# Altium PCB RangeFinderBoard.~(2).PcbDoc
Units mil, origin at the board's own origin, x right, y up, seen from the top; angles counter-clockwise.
Board outline 6000 x 4000 mil, 2 copper layers (Top Layer, Bottom Layer); 90 components, 55 nets, 346 pads, 0 vias.
Unrouted connection lines stored in the file: 222.
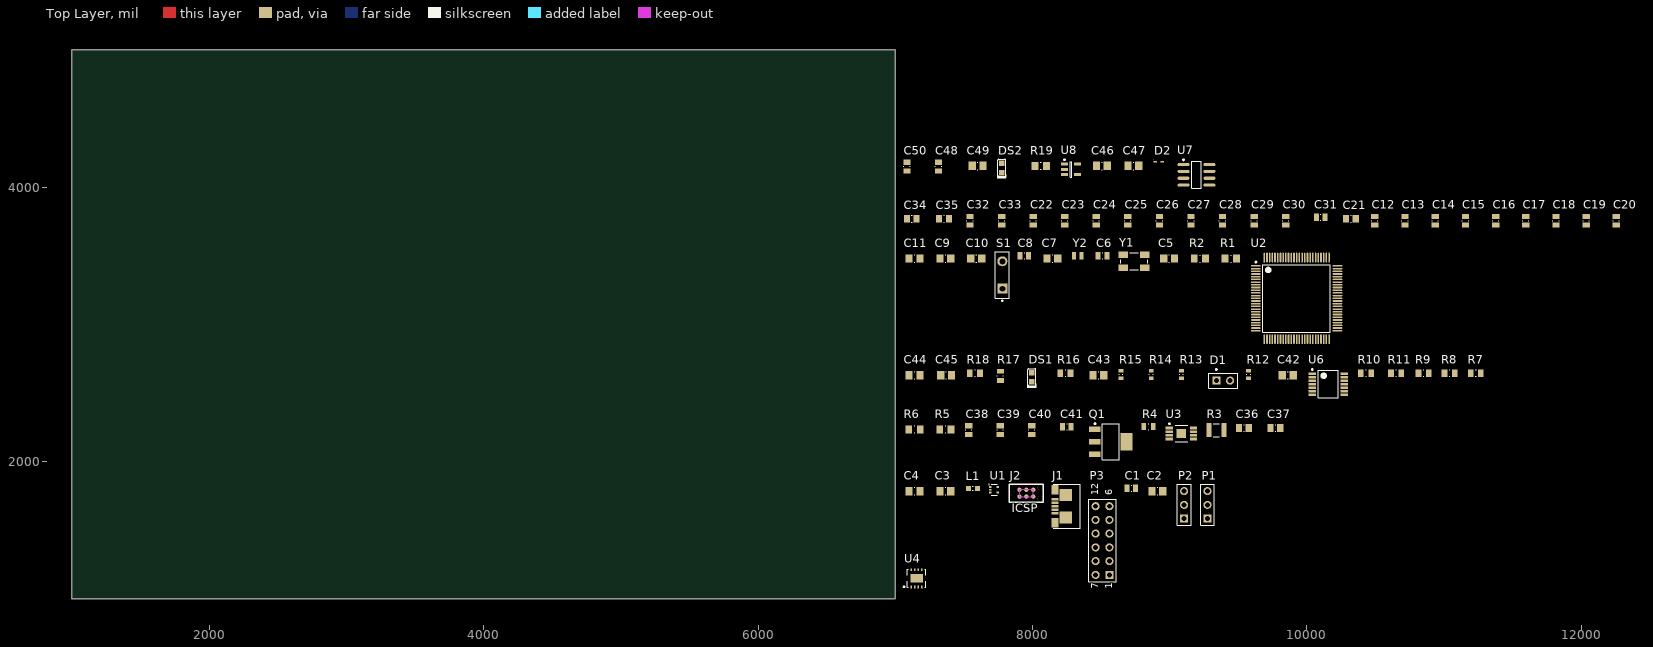
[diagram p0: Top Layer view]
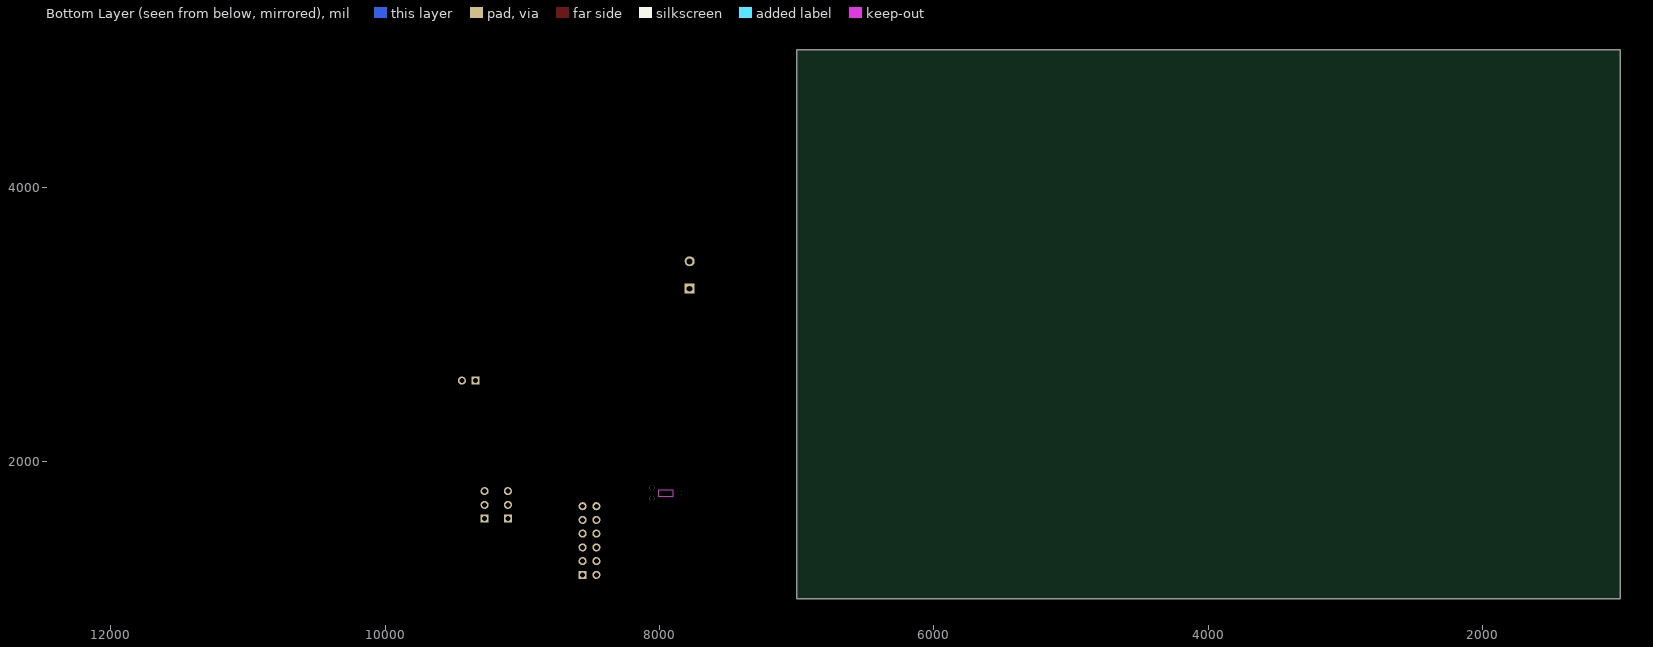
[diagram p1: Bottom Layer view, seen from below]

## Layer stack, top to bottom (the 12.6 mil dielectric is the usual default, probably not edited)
Top Solder: solder mask 0.4, Solder Resist, Dk 3.5
Top Layer: signal copper 1.4
Dielectric 1: dielectric 12.6, FR-4, Dk 4.8
Bottom Layer: signal copper 1.4
Bottom Solder: solder mask 0.4, Solder Resist, Dk 3.5

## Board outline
1000,1000 7000,1000 7000,5000 1000,5000

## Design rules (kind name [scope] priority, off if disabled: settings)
Clearance [All] p1: gap=10
PolygonConnect [All] p1: connectstyle=Relief reliefconductorwidth=10 reliefentries=4 polygonreliefangle="90 Angle" airgapwidth=10
RoomDefinition U_RangeFinderSystemPower [InComponentClass('U_RangeFinderSystemPower')] p1: confinementstyle=ConfineIn formatcopy=TRUE lockcomponents=FALSE outline 7045,3970 9350,3970 9350,4315 7045,4315
RoomDefinition U_RangeFinderMicroPower [InComponentClass('U_RangeFinderMicroPower')] p2: confinementstyle=ConfineIn formatcopy=TRUE lockcomponents=FALSE outline 7045,3690 12410,3690 12410,3920 7045,3920
RoomDefinition U_RangeFinderMicro [InComponentClass('U_RangeFinderMicro')] p3: confinementstyle=ConfineIn formatcopy=TRUE lockcomponents=FALSE outline 7045,2840 10275,2840 10275,3640 7045,3640
RoomDefinition U_LaserReceiver [InComponentClass('U_LaserReceiver')] p4: confinementstyle=ConfineIn formatcopy=TRUE lockcomponents=FALSE outline 7045,2445 11305,2445 11305,2790 7045,2790
RoomDefinition U_LaserOut [InComponentClass('U_LaserOut')] p5: confinementstyle=ConfineIn formatcopy=TRUE lockcomponents=FALSE outline 7045,1995 9890,1995 9890,2395 7045,2395
RoomDefinition RangeFinderTop [InComponentClass('RangeFinderTop')] p6: confinementstyle=ConfineIn formatcopy=TRUE lockcomponents=FALSE outline 7045,1060 9335,1060 9335,1945 7045,1945
RoutingVias [All] p1: holewidth=28 width=50 viastyle="Through Hole" minholewidth=28 minwidth=50 maxholewidth=28 maxwidth=50
SolderMaskExpansion [All] p1: expansion=4
Width [All] p1: maxlimit=10 minlimit=10 preferedwidth=10
30 further rules are at their usual default settings.

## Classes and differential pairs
component class U_RangeFinderSystemPower: C46 C47 C48 C49 C50 D2 DS2 R19 U7 U8 U9
component class U_RangeFinderMicro: C5 C6 C7 C8 C9 C10 C11 R1 R2 S1 U2 Y1 Y2
component class U_RangeFinderMicroPower: C12 C13 C14 C15 C16 C17 C18 C19 C20 C21 C22 C23 C24 C25 C26 C27 C28 C29 C30 C31 C32 C33 C34 C35
component class U_LaserReceiver: C42 C43 C44 C45 D1 DS1 R7 R8 R9 R10 R11 R12 R13 R14 R15 R16 R17 R18 U4 U5 U6 U?
component class U_LaserOut: C36 C37 C38 C39 C40 C41 LAS1 Q1 R3 R4 R5 R6 U3
component class RangeFinderTop: C1 C2 C3 C4 J1 J2 L1 P1 P2 P3 U1

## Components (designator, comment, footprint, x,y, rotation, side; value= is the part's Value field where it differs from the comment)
C1 "CAP 100nF 6.3V 0805(2012)" CAPC0805(2012)100_L 8720,1805 r0 top
C2 "CAP 1uF 6.3V 0805(2012)" CAPC0805(2012)100_M 8910,1785 r0 top
C3 "CAP 1uF 6.3V 0805(2012)" CAPC0805(2012)100_M 7365,1785 r0 top
C4 "CAP 10uF 6.3V 0805(2012)" CAPC0805(2012)100_M 7140,1785 r0 top
C5 "CAP 10pF 10V 0805(2012)" CAPC0805(2012)100_M 8995,3480 r0 top
C6 "CAP 3.9pF 10V 0805(2012)" CAPC0805(2012)75_L 8510,3500 r0 top
C7 "CAP 10pF 10V 0805(2012)" CAPC0805(2012)100_M 8145,3480 r0 top
C8 "CAP 3.9pF 10V 0805(2012)" CAPC0805(2012)75_L 7940,3500 r0 top
C9 "CAP 1.5uF 6.3V 0805(2012)" CAPC0805(2012)145_M 7365,3480 r0 top
C10 "CAP 100nF 0805(2012)" CAPC0805(2012)145_M 7590,3480 r0 top
C11 "CAP 1.5uF 6.3V 0805(2012)" CAPC0805(2012)145_M 7140,3480 r0 top
C12 "CAP 100nF 6.3V 0805(2012)" CAPC0805(2012)100_L 10495,3755 r90 top
C13 "CAP 100nF 6.3V 0805(2012)" CAPC0805(2012)100_L 10715,3755 r90 top
C14 "CAP 100nF 6.3V 0805(2012)" CAPC0805(2012)100_L 10935,3755 r90 top
C15 "CAP 100nF 6.3V 0805(2012)" CAPC0805(2012)100_L 11155,3755 r90 top
C16 "CAP 100nF 6.3V 0805(2012)" CAPC0805(2012)100_L 11375,3755 r90 top
C17 "CAP 100nF 6.3V 0805(2012)" CAPC0805(2012)100_L 11595,3755 r90 top
C18 "CAP 100nF 6.3V 0805(2012)" CAPC0805(2012)100_L 11815,3755 r90 top
C19 "CAP 100nF 6.3V 0805(2012)" CAPC0805(2012)100_L 12035,3755 r90 top
C20 "CAP 100nF 6.3V 0805(2012)" CAPC0805(2012)100_L 12255,3755 r90 top
C21 "CAP 4.7uF 6.3V 0805(2012)" CAPC0805(2012)145_N 10320,3770 r0 top
C22 "CAP 100nF 6.3V 0805(2012)" CAPC0805(2012)100_L 8005,3755 r90 top
C23 "CAP 100nF 6.3V 0805(2012)" CAPC0805(2012)100_L 8235,3755 r90 top
C24 "CAP 100nF 6.3V 0805(2012)" CAPC0805(2012)100_L 8465,3755 r90 top
C25 "CAP 100nF 6.3V 0805(2012)" CAPC0805(2012)100_L 8695,3755 r90 top
C26 "CAP 100nF 6.3V 0805(2012)" CAPC0805(2012)100_L 8925,3755 r90 top
C27 "CAP 100nF 6.3V 0805(2012)" CAPC0805(2012)100_L 9155,3755 r90 top
C28 "CAP 100nF 6.3V 0805(2012)" CAPC0805(2012)100_L 9385,3755 r90 top
C29 "CAP 100nF 6.3V 0805(2012)" CAPC0805(2012)100_L 9615,3755 r90 top
C30 "CAP 100nF 6.3V 0805(2012)" CAPC0805(2012)100_L 9845,3755 r90 top
C31 "CAP 100nF 6.3V 0805(2012)" CAPC0805(2012)100_L 10100,3780 r0 top
C32 "CAP 100nF 6.3V 0805(2012)" CAPC0805(2012)100_L 7545,3755 r90 top
C33 "CAP 100nF 6.3V 0805(2012)" CAPC0805(2012)100_L 7775,3755 r90 top
C34 "CAP 1uF 6.3V 0805(2012)" CAPC0805(2012)145_N 7120,3770 r0 top
C35 "CAP 1uF 6.3V 0805(2012)" CAPC0805(2012)145_N 7355,3770 r0 top
C36 "CAP 100nF 6.3V 0805(2012)" CAPC0805(2012)100_N 9540,2245 r0 top
C37 "CAP 10uF 6.3V 0805(2012)" CAPC0805(2012)145_N 9770,2245 r0 top
C38 "CAP 22nF 6.3V 0805(2012)" CAPC0805(2012)100_L 7535,2230 r90 top
C39 "CAP 22nF 6.3V 0805(2012)" CAPC0805(2012)100_L 7765,2230 r90 top
C40 "CAP 22nF 6.3V 0805(2012)" CAPC0805(2012)100_L 7995,2230 r90 top
C41 "CAP 22nF 6.3V 0805(2012)" CAPC0805(2012)100_L 8250,2255 r0 top
C42 "CAP 1nF 6.3V 0805(2012)" CAPC0805(2012)100_M 9860,2630 r0 top
C43 "CAP 1uF 6.3V 0805(2012)" CAPC0805(2012)100_M 8480,2630 r0 top
C44 "CAP 2.2uF 6.3V 0805(2012)" CAPC0805(2012)100_M 7140,2630 r0 top
C45 "CAP 100nF 6.3V 0805(2012)" CAPC0805(2012)100_M 7370,2630 r0 top
C46 "CAP 1uF 6.3V 0805(2012)" CAPC0805(2012)100_M 8505,4155 r0 top
C47 "CAP 10uF 6.3V 0805(2012)" CAPC0805(2012)145_M 8735,4155 r0 top
C48 "CAP 100nF 6.3V 0805(2012)" CAPC0805(2012)100_L 7315,4150 r90 top
C49 "CAP 1uF 6.3V 0805(2012)" CAPC0805(2012)100_M 7600,4155 r0 top
C50 "CAP 470pF 6.3V 0805(2012)" CAPC0805(2012)100_L 7085,4150 r90 top
D1 "Photo Sen" PIN2 9340,2590 r0 top
D2 "BAT41KFILM" BAT41KFILM 8920,4185 r0 top
DS1 "KP-1608SECK" KING-0603LED_ORANGE_V 7995,2615 r90 top
DS2 "APG1608CGKC/T" KING-LED0603-25-GREEN_V 7775,4140 r90 top
J1 "2173157-3" 2173157-3 8165,1675 r90 top
J2 "ICSP-6 No Legs" TC2030-IDC-NL 7955,1745 r0 top
L1 "LI0603E470R-10" LI0603E470R-10 7565,1805 r0 top
P1 "Header 3" HDR1X3 9275,1585 r90 top
P2 "Header 3" HDR1X3 9105,1585 r90 top
P3 "Header 6X2A" HDR2X6_CEN 8560,1175 r90 top
Q1 "BSP318SH6327XTSA1" BSP318SH6327XTSA1--SOT230P700X180-4N 8570,2145 r0 top
R1 "22R 5% 0805(2012)" RESC0805(2012)_M 9445,3480 r0 top
R2 "22R 5% 0805(2012)" RESC0805(2012)_M 9220,3480 r0 top
R3 "100R 5% 1210(3225)" RESC1210(3225)_L 9340,2230 r0 top
R4 "Jumper 0805(2012)" RESC0805(2012)_L 8845,2255 r0 top
R5 "100R 5% 0805(2012)" RESC0805(2012)_M 7365,2235 r0 top
R6 "100R 5% 0805(2012)" RESC0805(2012)_M 7140,2235 r0 top
R7 "Jumper 0805(2012)" RESC0805(2012)_N 11230,2645 r0 top
R8 "Jumper 0805(2012)" RESC0805(2012)_N 11040,2645 r0 top
R9 "51R 5% 0805(2012)" RESC0805(2012)_N 10850,2645 r0 top
R10 "51R 5% 0805(2012)" RESC0805(2012)_N 10430,2645 r0 top
R11 "51R 5% 0805(2012)" RESC0805(2012)_N 10650,2645 r0 top
R12 "100R 5% 0603(1608)" RESC0603(1608)_L 9575,2635 r90 top
R13 "100R 5% 0603(1608)" RESC0603(1608)_L 9085,2635 r90 top
R14 "100R 5% 0603(1608)" RESC0603(1608)_L 8865,2635 r90 top
R15 "100R 5% 0603(1608)" RESC0603(1608)_L 8645,2635 r90 top
R16 "Jumper 0805(2012)" RESC0805(2012)_N 8240,2645 r0 top
R17 "100K 5% 0805(2012)" RESC0805(2012)_L 7765,2625 r90 top
R18 "51R 5% 0805(2012)" RESC0805(2012)_N 7580,2645 r0 top
R19 "470K 5% 0805(2012)" RESC0805(2012)_M 8060,4155 r0 top
S1 "SW-PB" SPST-2 7780,3360 r90 top
U1 "TPD2E001-SOT_DRL-5" TPD2E001DRLR 7720,1795 r0 top
U2 "STM32F427VIT7TR" STM-LQFP100_N 9925,3190 r0 top
U3 "MIC44F18YMME" MIC44F18YMME--TSOP65P490X108_HS-9N 9085,2205 r0 top
U4 "MAX3658AETA+T" MAX3658AETA+T--QFN0P300X300X80_HS-9N 7155,1150 r0 top
U6 "TDC7200PW" TDC7200PW--TSOP65P640X120-14N 10155,2565 r0 top
U7 "LT1129CS8-5#PBF" LT-S8-8_N 9195,4090 r0 top
U8 "LTC4411ES5#TRMPBF" LT-S5-5-TSOT-23_N 8280,4130 r0 top
Y1 "ABM3B-8.000MHZ-10-1-U-T" "ABM3B Series" 8740,3460 r0 top
Y2 "ABS06-107-32.768KHZ-T" ABS06-107 8330,3500 r0 top

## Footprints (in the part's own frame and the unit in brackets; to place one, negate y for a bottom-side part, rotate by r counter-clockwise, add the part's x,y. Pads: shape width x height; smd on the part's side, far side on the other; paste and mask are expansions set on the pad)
2173157-3 [mm] "Splash Proof Micro USB B-Type low MOQ"
  rect 0.5x1.3 smd: 1(-1.3,0) 2(-0.65,0) 3(0,0) 4(0.65,0) 5(1.3,0)
  rect 1.75x1.3 smd: EP1(-3.075,0) EP2(3.075,0)
  rect 2.25x2.3 smd: SH(-2.075,-1.95) SH(2.075,-1.95)
  silkscreen extent -4.1,-4.65 4.1,0.35, body extent -4.1,-4.76 4.1,0.35, height 3.76
"ABM3B Series" [mm] "Abaracon Corporation ABM3B Series Crystal Oscillators"
  rect 1.8x1.2 smd: 1(-2,-1.2) 2(2,-1.2) 3(2,1.2) 4(-2,1.2)
  silkscreen extent -2.5,-1.6 2.5,1.6, body extent -2.5,-1.59 2.5,1.59, height 1.1
ABS06-107 [mm] "Abracon Corporations ABS06-107 Tuning Fork Crystak"
  rect 0.75x1.4 smd: 1(-0.725,0) 2(0.725,0)
  body extent -1,-0.6 1,0.6, height 0.61
BAT41KFILM [mm] "DIODE SCHOTTKY 100V 200MA SOD523"
  rect 0.65x0.3 smd: 1(-0.675,0) 2(0.675,0)
  silkscreen extent -0.98,0.45 -0.97,0.45, body extent -0.8,-0.4 0.8,0.4, height 0.7
BSP318SH6327XTSA1--SOT230P700X180-4N [mm] "SOT223, 4-Leads, Body 6.50x7.00mm (avg), Pitch 2.30mm, IPC Medium Density"
  rect 2.15x1 smd: 1(-2.925,2.3) 2(-2.925,0) 3(-2.925,-2.3)
  rect 2.15x3.25 smd: 4(2.925,0)
  silkscreen extent -3.05,-3.35 1.55,3.47, body extent -1.85,-3.35 1.85,3.35, height 1.8
CAPC0805(2012)75_L [mm] "Chip Capacitor, Body 2.0x1.2mm, Height 0.75mm, IPC High Density"
  rect 0.95x1.35 smd: 1(-0.8,0) 2(0.8,0)
  silkscreen extent -0.05,-0.58 0.05,0.58, body extent -1.1,-0.72 1.1,0.72, height 0.75
CAPC0805(2012)100_L [mm] "Chip Capacitor, Body 2.0x1.2mm, Height 1.0mm, IPC High Density"
  rect 0.95x1.35 smd: 1(-0.8,0) 2(0.8,0)
  silkscreen extent -0.05,-0.58 0.05,0.58, body extent -1.1,-0.72 1.1,0.72, height 1
CAPC0805(2012)100_M [mm] "Chip Capacitor, Body 2.0x1.2mm, Height 1.0mm, IPC Low Density"
  rect 1.35x1.55 smd: 1(-1,0) 2(1,0)
  silkscreen extent -0.05,-0.67 0.05,0.67, body extent -1.1,-0.72 1.1,0.72, height 1
CAPC0805(2012)100_N [mm] "Chip Capacitor, Body 2.0x1.2mm, Height 1.0mm, IPC Medium Density"
  rect 1.15x1.45 smd: 1(-0.9,0) 2(0.9,0)
  silkscreen extent -0.05,-0.62 0.05,0.63, body extent -1.1,-0.72 1.1,0.73, height 1
CAPC0805(2012)145_M [mm] "Chip Capacitor, Body 2.0x1.2mm, Height 1.45mm, IPC Low Density"
  rect 1.35x1.55 smd: 1(-1,0) 2(1,0)
  silkscreen extent -0.05,-0.67 0.05,0.67, body extent -1.1,-0.72 1.1,0.72, height 1.45
CAPC0805(2012)145_N [mm] "Chip Capacitor, Body 2.0x1.2mm, Height 1.45mm, IPC Medium Density"
  rect 1.15x1.45 smd: 1(-0.9,0) 2(0.9,0)
  silkscreen extent -0.05,-0.62 0.05,0.63, body extent -1.1,-0.72 1.1,0.73, height 1.45
HDR1X3 [mm] "Connector; Header; 3 Position"
  rect 1.5x1.5 hole 0.9: 1(0,0)
  round 1.5 hole 0.9: 2(2.54,0) 3(5.08,0)
  silkscreen extent -1.27,-1.27 6.35,1.27
HDR2X6_CEN [mm] "Connector; Header; 6x2 Position"
  rect 1.5x1.5 hole 0.9: 1(0,0)
  round 1.5 hole 0.9: 2(2.54,0) 3(5.08,0) 4(7.62,0) 5(10.16,0) 6(12.7,0) 7(0,2.54) 8(2.54,2.54) 9(5.08,2.54) 10(7.62,2.54) 11(10.16,2.54) 12(12.7,2.54)
  silkscreen extent -1.27,-1.27 13.97,3.81
KING-0603LED_ORANGE_V [mm] "SMT LED, 2-Leads, Body 1.6x0.8mm (0603-Size)"
  rect 1x1 smd paste+0 mask+0: 1(0.85,0) 2(-0.85,0)
  silkscreen extent -1.97,-0.85 1.6,0.85, body extent -0.92,-0.53 1.09,0.53, height 1.1
KING-LED0603-25-GREEN_V [mm] "LED, SMT, Body 1.6 x 0.8 mm, 0.25mm Thickness"
  rect 1x1 smd paste+0 mask+0: 1(0.85,0) 2(-0.85,0)
  silkscreen extent -1.97,-0.85 1.6,0.85, body extent -0.8,-0.4 0.8,0.4, height 0.25
LI0603E470R-10 [mm] "FERRITE CHIP 47 OHMS 500MA 0603"
  rect 0.92x0.96 smd: 1(-0.84,0) 2(0.84,0)
  silkscreen extent -0.1,-0.38 0.1,0.38, body extent -0.88,-0.48 0.87,0.47, height 0.95
LT-S5-5-TSOT-23_N [mm] "SOT23, 5-Leads, Body 2.90x1.63mm, Pitch 0.95mm, IPC Medium Density"
  rect 1.3x0.55 smd: 1(-1.2,0.95) 2(-1.2,0) 3(-1.2,-0.95) 4(1.2,-0.95) 5(1.2,0.95)
  silkscreen extent -1.32,-1.45 0.15,1.9, body extent -0.87,-1.45 0.87,1.45, height 1
LT-S8-8_N [mm] "SOIC, 8-Leads, Body 4.9x3.9mm, Pitch 1.27mm, IPC Medium Density"
  oval 2.2x0.6 smd: 1(-2.4,1.905) 2(-2.4,0.635) 3(-2.4,-0.635) 4(-2.4,-1.905) 5(2.4,-1.905) 6(2.4,-0.635) 7(2.4,0.635) 8(2.4,1.905)
  silkscreen extent -2.52,-2.5 0.9,2.88, body extent -2,-2.5 2,2.5, height 1.76
MAX3658AETA+T--QFN0P300X300X80_HS-9N [mm] "QFN, 8-Leads, Body 3.00x3.00mm, Pitch 0.65mm/0.00mm, Thermal Pad 2.30x1.50mm, IPC Medium Density"
  rect 0.3x0.5 smd: 1(-0.975,-1.6) 2(-0.325,-1.6) 3(0.325,-1.6) 4(0.975,-1.6) 5(0.975,1.6) 6(0.325,1.6) 7(-0.325,1.6) 8(-0.975,1.6)
  rect 2.3x1.5 smd: 9(0,0)
  silkscreen extent -2.42,-1.7 1.7,1.7, body extent -1.55,-1.55 1.55,1.55, height 0.8
MIC44F18YMME--TSOP65P490X108_HS-9N [mm] "TSOP, 8-Leads, Body 3.00x3.00mm, Pitch 0.65mm, Thermal Pad 1.70x1.73mm, IPC Medium Density"
  rect 1.35x0.55 smd: 1(-2.225,0.975) 2(-2.225,0.325) 3(-2.225,-0.325) 4(-2.225,-0.975) 5(2.225,-0.975) 6(2.225,-0.325) 7(2.225,0.325) 8(2.225,0.975)
  rect 1.73x1.7 smd: 9(0,0)
  silkscreen extent -2.35,-1.55 1.15,1.92, body extent -1.55,-1.55 1.55,1.55, height 1.08
PIN2 [mm] "Photosensitive Diode; 2 Leads"
  rect 1.5x1.5 hole 0.9: 1(0,0)
  round 1.5 hole 0.9: 2(2.54,0)
  silkscreen extent -1.4,-1.4 3.94,2.17
RESC0603(1608)_L [mm] "Chip Resistor, Body 1.6x0.8mm, IPC High Density"
  rect 0.7x0.9 smd: 1(-0.7,0) 2(0.7,0)
  silkscreen extent -0.05,-0.35 0.05,0.35, body extent -0.85,-0.47 0.85,0.47, height 0.6
RESC0805(2012)_L [mm] "Chip Resistor, Body 2.0x1.3mm, IPC High Density"
  rect 0.85x1.3 smd: 1(-0.85,0) 2(0.85,0)
  silkscreen extent -0.05,-0.55 0.05,0.55, body extent -1.1,-0.67 1.1,0.68, height 0.7
RESC0805(2012)_M [mm] "Chip Resistor, Body 2.0x1.3mm, IPC Low Density"
  rect 1.25x1.5 smd: 1(-1.05,0) 2(1.05,0)
  silkscreen extent -0.05,-0.65 0.05,0.65, body extent -1.1,-0.67 1.1,0.67, height 0.7
RESC0805(2012)_N [mm] "Chip Resistor, Body 2.0x1.3mm, IPC Medium Density"
  rect 1.05x1.4 smd: 1(-0.95,0) 2(0.95,0)
  silkscreen extent -0.05,-0.6 0.05,0.6, body extent -1.1,-0.67 1.1,0.68, height 0.7
RESC1210(3225)_L [mm] "Chip Resistor, Body 3.2x2.5mm, IPC High Density"
  rect 0.95x2.6 smd: 1(-1.4,0) 2(1.4,0)
  silkscreen extent -0.55,-1.2 0.55,1.2, body extent -1.7,-1.35 1.7,1.35, height 0.71
SPST-2 [mm] "Switch; 2 Leads"
  rect 1.85x1.85 hole 1.1: 1(-2.54,0)
  round 1.85 hole 1.1: 2(2.54,0)
  silkscreen extent -4.89,-1.27 4.28,1.27
STM-LQFP100_N [mm] "Thin QFP, 100-Leads, Body 14x14mm, Pitch 0.5mm, IPC Medium Density"
  oval 1.8x0.3 smd: 1(-7.55,6) 2(-7.55,5.5) 3(-7.55,5) 4(-7.55,4.5) 5(-7.55,4) 6(-7.55,3.5) 7(-7.55,3) 8(-7.55,2.5) 9(-7.55,2) 10(-7.55,1.5) 11(-7.55,1) 12(-7.55,0.5) 13(-7.55,0) 14(-7.55,-0.5) 15(-7.55,-1) 16(-7.55,-1.5) 17(-7.55,-2) 18(-7.55,-2.5) 19(-7.55,-3) 20(-7.55,-3.5) 21(-7.55,-4) 22(-7.55,-4.5) 23(-7.55,-5) 24(-7.55,-5.5) 25(-7.55,-6) 51(7.55,-6) 52(7.55,-5.5) 53(7.55,-5) 54(7.55,-4.5) 55(7.55,-4) 56(7.55,-3.5) 57(7.55,-3) 58(7.55,-2.5) 59(7.55,-2) 60(7.55,-1.5) 61(7.55,-1) 62(7.55,-0.5) 63(7.55,0) 64(7.55,0.5) 65(7.55,1) 66(7.55,1.5) 67(7.55,2) 68(7.55,2.5) 69(7.55,3) 70(7.55,3.5) 71(7.55,4) 72(7.55,4.5) 73(7.55,5) 74(7.55,5.5) 75(7.55,6)
  oval 0.3x1.8 smd: 26(-6,-7.55) 27(-5.5,-7.55) 28(-5,-7.55) 29(-4.5,-7.55) 30(-4,-7.55) 31(-3.5,-7.55) 32(-3,-7.55) 33(-2.5,-7.55) 34(-2,-7.55) 35(-1.5,-7.55) 36(-1,-7.55) 37(-0.5,-7.55) 38(0,-7.55) 39(0.5,-7.55) 40(1,-7.55) 41(1.5,-7.55) 42(2,-7.55) 43(2.5,-7.55) 44(3,-7.55) 45(3.5,-7.55) 46(4,-7.55) 47(4.5,-7.55) 48(5,-7.55) 49(5.5,-7.55) 50(6,-7.55) 76(6,7.55) 77(5.5,7.55) 78(5,7.55) 79(4.5,7.55) 80(4,7.55) 81(3.5,7.55) 82(3,7.55) 83(2.5,7.55) 84(2,7.55) 85(1.5,7.55) 86(1,7.55) 87(0.5,7.55) 88(0,7.55) 89(-0.5,7.55) 90(-1,7.55) 91(-1.5,7.55) 92(-2,7.55) 93(-2.5,7.55) 94(-3,7.55) 95(-3.5,7.55) 96(-4,7.55) 97(-4.5,7.55) 98(-5,7.55) 99(-5.5,7.55) 100(-6,7.55)
  silkscreen extent -7.67,-6.25 6.25,6.82, body extent -7,-7 7,7, height 1.6
TC2030-IDC-NL [mm] "Tag-Connect 6-Pin with No Legs (PN# TC2030-IDC-NL)"
  round 0.9 hole 0.995 unplated: 0(-2.54,0.635) 0(2.54,-0.381) 0(2.54,1.651)
  round 0.79 smd paste-0.39: 1(-1.27,0) 2(-1.27,1.27) 3(0,0) 4(0,1.27) 5(1.27,0) 6(1.27,1.27)
  Keep-Out Layer region: -1.27,0 1.27,0 1.27,1.27 -1.27,1.27
  silkscreen extent -3.17,-1.02 3.17,2.29
TDC7200PW--TSOP65P640X120-14N [mm] "TSOP, 14-Leads, Body 5.00x4.40mm, Pitch 0.65mm, IPC Medium Density"
  rect 1.4x0.45 smd: 1(-2.95,1.95) 2(-2.95,1.3) 3(-2.95,0.65) 4(-2.95,0) 5(-2.95,-0.65) 6(-2.95,-1.3) 7(-2.95,-1.95) 8(2.95,-1.95) 9(2.95,-1.3) 10(2.95,-0.65) 11(2.95,0) 12(2.95,0.65) 13(2.95,1.3) 14(2.95,1.95)
  silkscreen extent -3.07,-2.55 1.85,2.85, body extent -2.25,-2.55 2.25,2.55, height 1.2
TPD2E001DRLR [mm] "SOTFL, 5-Flat Leads, Body 1.2x1.6x0.6mm, Pitch 0.5mm, TI Recommended"
  rect 0.45x0.3 smd: 1(-0.675,0.5) 2(-0.675,0) 3(-0.675,-0.5) 4(0.675,-0.5) 5(0.675,0.5)
  silkscreen extent -1,-1 0.55,1.05, body extent -0.65,-0.85 0.65,0.85, height 0.6

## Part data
C1 C12 C13 C14 C15 C16 C17 C18 C19 C20 C22 C23 C24 C25 C26 C27 C28 C29 C30 C31 C32 C33 C48: library part CMP-1036-04390-1, "CAP 100nF 6.3V ±5% 0805 (2012 Metric) Thickness 1mm SMD"
C2 C3 C46 C49: library part CMP-1036-04730-1, "CAP 1uF 6.3V ±5% 0805 (2012 Metric) Thickness 1mm SMD"
C4: library part CMP-1036-04730-1, "CAP 10uF 6.3V ±5% 0805 (2012 Metric) Thickness 1mm SMD"
C5 C7: library part CMP-1036-00821-1, "CAP 10pF 10V ±0.25pF 0805 (2012 Metric) Thickness 1mm SMD"
C6 C8: library part CMP-1036-00455-1, "CAP 3.9pF 10V ±0.1pF 0805 (2012 Metric) Thickness 0.75mm SMD"
C9 C10 C11: library part CMP-1036-04784-1, "CAP 1.5uF 6.3V ±20% 0805 (2012 Metric) Thickness 1.45mm SMD"
C21: library part CMP-1036-04781-1, "CAP 4.7uF 6.3V ±5% 0805 (2012 Metric) Thickness 1.45mm SMD"
C34 C35: library part CMP-1036-04781-1, "CAP 1uF 6.3V ±5% 0805 (2012 Metric) Thickness 1.45mm SMD"
C36: library part CMP-1036-04391-1, "CAP 100nF 6.3V ±10% 0805 (2012 Metric) Thickness 1mm SMD"
C37: library part CMP-1036-04781-1, "CAP 10uF 6.3V ±5% 0805 (2012 Metric) Thickness 1.45mm SMD"
C38 C39 C40 C41: library part CMP-1036-04030-1, "CAP 22nF 6.3V ±5% 0805 (2012 Metric) Thickness 1mm SMD"
C42: library part CMP-1036-02947-1, "CAP 1nF 6.3V ±5% 0805 (2012 Metric) Thickness 1mm SMD"
C43: library part CMP-1036-02947-1, "CAP 1uF 6.3V ±5% 0805 (2012 Metric) Thickness 1mm SMD"
C44: library part CMP-1036-02947-1, "CAP 2.2unF 6.3V ±5% 0805 (2012 Metric) Thickness 1mm SMD"
C45: library part CMP-1036-02947-1, "CAP 100nF 6.3V ±5% 0805 (2012 Metric) Thickness 1mm SMD"
C47: library part CMP-1036-04784-1, "CAP 10uF 6.3V ±5% 0805 (2012 Metric) Thickness 1.45mm SMD"
C50: library part CMP-1036-02639-1, "CAP 470pF 6.3V ±5% 0805 (2012 Metric) Thickness 1mm SMD"
D1: "Photosensitive Diode"
D2: "DIODE SCHOTTKY 100V 200MA SOD523"
DS1: library part CMP-0404-00002-1, "LED, SMT, 0603(1608), 1.1mm thickness, Orange"
DS2: library part CMP-0239-00001-1, "LED, SMT, 0603(1608), 0.25mm Thickness, Green"
J1: "USB Connectors SPLASH PROOF MICRO 5P USB B-TYPE"
J2: "6 Pin Connector"
L1: "FERRITE CHIP 47 OHMS 500MA 0603"
P1 P2: "Header, 3-Pin"
P3: "Header, 6-Pin, Dual row"
Q1: "MOSFET N-Ch 60V 2.6A SOT-223-3"
R1 R2: library part CMP-1013-00034-1, "22R 0.125W 5% 0805 (2012 Metric)  SMD"
R3: library part CMP-1015-00050-1, "100R 0.5W 5% 1210 (3225 Metric)  SMD"
R4 R7 R8 R16: library part CMP-1013-00001-1, "Jumper 0805 (2012 Metric)"
R5 R6: library part CMP-1013-00050-1, "100R 0.125W 5% 0805 (2012 Metric)  SMD"
R9 R10 R11 R18: library part CMP-1013-00043-1, "51R 0.125W 5% 0805 (2012 Metric)  SMD"
R12 R13 R14 R15: library part CMP-1012-00050-1, "100R 0.1W 5% 0603 (1608 Metric)  SMD"
R17: library part CMP-1013-00122-1, "100K 0.125W 5% 0805 (2012 Metric)  SMD"
R19: library part CMP-1013-00138-1, "470K 0.125W 5% 0805 (2012 Metric)  SMD"
S1: "Switch"
U1: library part TPD2E001DRLR, "TVS DIODE 5.5VWM 100VC SOT5"
U2: library part CMP-0243-00026-2, "ARM Cortex-M4 32-bit MCU+FPU, 210 DMIPS, 2048 kB Flash, 256 kB Internal RAM, 82 I/Os, 100-pin LQFP, -40 to 105 degC, Tape and Reel"
U3: "Gate Drivers 3A High Speed MOSFET Driver"
U4: "IC AMP TRANSIMPEDANCE 8-TDFN"
U6: "STATIC ULTRASONIC FLOWMETER AF"
U7: library part CMP-0476-01544-1, "Micropower Low Dropout Regulator with Shutdown, 4.15 to 30 V Vin, 5 V Vout, 8-pin SOIC (S8-8), 0 to 125 degC, Pb-Free"
U8: library part CMP-0479-00414-1, "Integrated Switch: Replaces Power Supply OR, 2.6 to 5.5 V Vin, 5-pin SOT23 (S5-5), -40 to 85 degC, Pb-Free, Mini Tape and Reel"
Y1: library part "ABM3B Series", "CRYSTAL 8MHZ 10PF SMD"
Y2: library part ABS06-107, "CRYSTAL 32.768 KHZ 4PF SMD"

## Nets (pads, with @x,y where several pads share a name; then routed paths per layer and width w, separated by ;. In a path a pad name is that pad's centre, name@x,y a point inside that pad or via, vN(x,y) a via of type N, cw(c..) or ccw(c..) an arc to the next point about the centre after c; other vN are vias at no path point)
3V3: C12.2 C13.2 C14.2 C15.2 C16.2 C17.2 C18.2 C19.2 C20.2 C21.2 C22.2 C23.2 C24.2 C25.2 C26.2 C27.2 C28.2 C29.2 C30.2 C31.2 C32.2 C33.2 C34.2 C35.2 C44.2 C45.2 C49.2 J2.1 P1.3 P2.3 R8.1 R10.2 R19.2 U2.11 U2.19 U2.21 U2.22 U2.28 U2.50 U2.75 U2.100 U4.1 U6.14
5V: C47.2 C48.2 U7.1 U7.2
AVG_OPTIC: R7.2 R16.1 R17.2 U4.4
GND: C1.1 C2.1 C3.1 C4.1 C5.2 C6.1 C7.2 C8.1 C9.1 C10.1 C11.1 C12.1 C13.1 C14.1 C15.1 C16.1 C17.1 C18.1 C19.1 C20.1 C21.1 C22.1 C23.1 C24.1 C25.1 C26.1 C27.1 C28.1 C29.1 C30.1 C31.1 C32.1 C33.1 C34.1 C35.1 C36.1 C37.1 C38.1 C39.1 C40.1 C41.1 C42.1 C43.1 C44.1 C45.1 C46.1 C47.1 C48.1 C49.1 C50.1 DS2.2 J1.5 J2.5 L1.1 P1.1 P2.1 P3.5 P3.6 P3.11 P3.12 R6.1 R11.1 R14.2 R15.1 R17.1 R18.1 S1.2 U1.4 U2.10 U2.20 U2.27 U2.74 U2.99 U3.6 U3.7 U4.5 U4.8 U4.9 U6.7 U7.3 U7.6 U7.7 U8.2 U8.3 Y1.2 Y1.4
NetC1_2: C1.2 C2.2 P3.1 P3.2 P3.7 P3.8 U8.1
NetC5_1: C5.1 U2.12 Y1.3
NetC6_2: C6.2 U2.8 Y2.2
NetC7_1: C7.1 U2.13 Y1.1
NetC8_2: C8.2 U2.9 Y2.1
NetC9_2: C9.2 U2.49
NetC10_2: C10.2 J2.3 S1.1 U2.14
NetC11_2: C11.2 U2.73
NetC38_2: C38.2 C39.2 C40.2 C41.2 Q1.2 Q1.4 R3.1
NetC42_2: C42.2 D1.2 U4.3
NetC43_2: C43.2 U6.13
NetC50_2: C50.2
NetD1_1: D1.1 U4.2
NetDS1_1: DS1.1 R4.1 U6.2
NetDS1_2: DS1.2 R18.2
NetDS2_1: DS2.1 R19.1 U8.4
NetJ1_2: J1.2 R1.1 U1.5
NetJ1_3: J1.3 R2.1 U1.3
NetJ1_EP1: J1.EP1 J1.EP2 J1.SH L1.2
NetJ2_2: J2.2 U2.72
NetJ2_4: J2.4 U2.76
NetJ2_6: J2.6 U2.89
NetLAS1_1: Q1.3
NetP1_2: P1.2 U2.37
NetP2_2: P2.2 U2.94
NetQ1_1: Q1.1 U3.1 U3.8
NetR1_2: R1.2 U2.70
NetR2_2: R2.2 U2.71
NetR4_2: R4.2 U2.33 U3.4
NetR5_1: R5.1 R6.2 U3.5
NetR7_1: R7.1 R8.2 R9.2
NetR9_1: R9.1 R11.2
NetR10_1: R10.1 U4.6
NetR12_1: R12.1 R14.1 U6.4
NetR12_2: R12.2
NetR13_1: R13.1 U4.7
NetR13_2: R13.2 R15.2
NetR16_2: R16.2 U2.15
NetU2_1: U2.1 U6.12
NetU2_3: U2.3 U6.11
NetU2_4: U2.4 U6.9
NetU2_5: U2.5 U6.10
NetU2_39: U2.39 U6.3
NetU2_40: U2.40 U6.1
NetU2_41: U2.41 U6.8
NetU2_66: U2.66 U6.5
USART3_RX: P3.4 P3.10 U2.79
USART3_TX: P3.3 P3.9 U2.78
V_LAS: R5.2
V_RAW: C36.2 C37.2 C46.2 D2.1 R3.2 U3.2 U7.5 U7.8 U8.5
V_USB: C3.2 C4.2 D2.2 J1.1 U1.1 U2.68
pads on no net: J1.4 J2.0 U1.2 U2.2 U2.6 U2.7 U2.16 U2.17 U2.18 U2.23 U2.24 U2.25 U2.26 U2.29 U2.30 U2.31 U2.32 U2.34 U2.35 U2.36 U2.38 U2.42 U2.43 U2.44 U2.45 U2.46 U2.47 U2.48 U2.51 U2.52 U2.53 U2.54 U2.55 U2.56 U2.57 U2.58 U2.59 U2.60 U2.61 U2.62 U2.63 U2.64 U2.65 U2.67 U2.69 U2.77 U2.80 U2.81 U2.82 U2.83 U2.84 U2.85 U2.86 U2.87 U2.88 U2.90 U2.91 U2.92 U2.93 U2.95 U2.96 U2.97 U2.98 U3.3 U3.9 U6.6 U7.4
